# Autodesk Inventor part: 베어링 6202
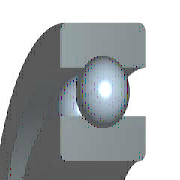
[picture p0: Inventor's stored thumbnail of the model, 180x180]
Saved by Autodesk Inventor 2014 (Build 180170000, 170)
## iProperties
Created: 2015-12
Part Number: 베어링 6202
Material: 강철, 연강
Description: 깊은 그루브 볼 베어링
Document SubType Name: Modeling
Standard: KS B 2023
Designer: mdu
Standards Organization: KS
Language: ko-KR
Size Designation: 6202 - 15 x 35 x 11
Categories: <MemberInstance><Categories><Category DisplayName="샤프트 부품" InternalName="7f7aeb1f-a693-4053-b835-cee3144e0d98" Mnemonic="SHFT"><Category DisplayName="베어링" Inter
Density: 7.86 g/cm^3
Mass: 42.4004 g
Surface Area: 51.5584 cm^2
Volume: 5.39445 cm^3
Appearance: 강철
Company: 한국ATC센터
IsCustomPart: 1
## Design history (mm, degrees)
sketch "스케치" dims "d0" = 5.2 (= -0.26 x WD + 0.26 x BD)
  geometry: L1 (2.9, 12.5)-(8.1, 12.5); L2 (5.5, 12.5)-(5.5, 9.9); L3 (5.5, 12.5)-(5.5, 15.1); L4 (3.568, 10.76)-(0, 10.76); L5 (0, 7.5)-(11, 7.5); L6 (3.568, 14.24)-(0, 14.24); L7 (0, 17.5)-(11, 17.5); L8 (11, 7.5)-(11, 10.76); L9 (7.432, 10.76)-(11, 10.76); L10 (7.432, 14.24)-(11, 14.24); L11 (11, 17.5)-(11, 14.24); L12 (-1.4, 0)-(8.4, 0) reference; L13 (0, -0.3)-(0, 5.3) reference
  constraints: 22 end point, 4 point on line, 2 collinear, 2 perpendicular, 2 symmetric about line, 1 midpoint, 1 parallel, 14 other
  dimensions: "d9" = 15 diameter of L5 L12 (= WD); "d11" = 35 diameter of L7 L12 (= BD); "d12" = 11 distance between parallel lines of L8 L13 (= KB); "d13" = 21.52 diameter of L9 L12 (= 0.326 x BD + 0.674 x WD)
revolve "본체" stored, may be unused: angle "d6" = 90 deg
revolve "볼" stored, may be unused: angle "d7" = 90 deg
pattern_circular "IDS_ARRAYBALL[SIMPL:T]" dims angle "d3" = 360 deg
body "Solid1"
fillet "모깎기1" dims "d1" = 0.6 (= KRS)
other parameters: "WD" = 15 [user parameter; used in 5 equation terms], "BD" = 35 [user parameter; used in 5 equation terms], "KB" = 11 [user parameter; used in 1 equation term], "KRS" = 0.6 [user parameter; used in 1 equation term], "d4" = 0, "d5" = 0, "d8" = 0, "d14" = 0, "d15" = 0, "BBA" = 0 [user parameter], "BC0" = 3750000 [user parameter], "BC" = 7800000 [user parameter], "BR" = 17.5 (= 0.5 x BD) [user parameter], "WR" = 7.5 (= 0.5 x WD) [user parameter]
